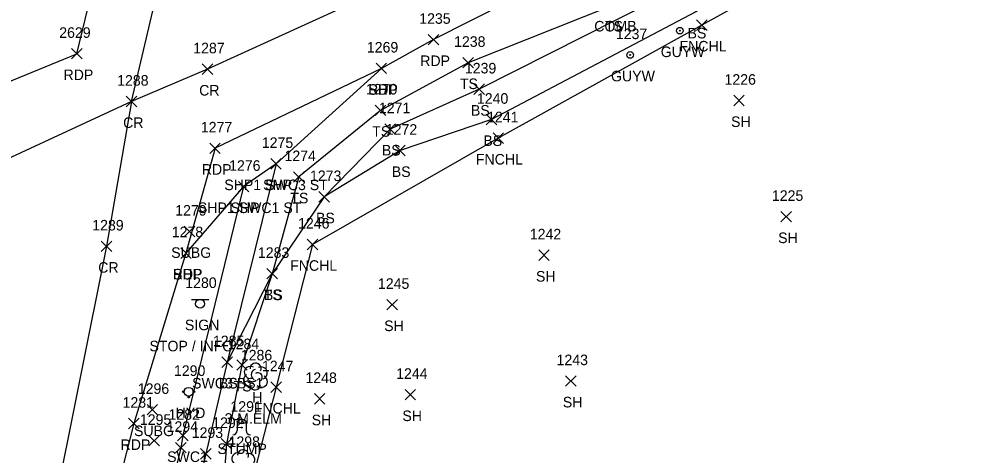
# Model space of a CAD drawing. Extents: x 1477930 to 1480780, y 774090 to 784647.
# Drawn here: x 1479397 to 1479576.9, y 774628 to 774710.6 of the extents above; entities that cross this region are included whole.
import ezdxf

# ---------------------------------------------------------------- set-up
doc = ezdxf.new("R2010")
doc.units = 0
for name, color, linetype in [('L_A', 7, 'Continuous'), ('L_C', 7, 'Continuous'), ('L_I', 7, 'Continuous'), ('L_TIC', 7, 'Continuous'), ('LELB', 7, 'Continuous'), ('LFNC', 7, 'Continuous'), ('LSH', 7, 'Continuous'), ('LTD', 7, 'Continuous'), ('LTS', 7, 'Continuous'), ('P_A', 7, 'Continuous'), ('P_I', 7, 'Continuous'), ('P_TIC', 7, 'Continuous'), ('PET', 7, 'Continuous'), ('PRC', 7, 'Continuous'), ('PSP', 7, 'Continuous'), ('R_A', 7, 'Continuous'), ('R_I', 7, 'Continuous'), ('R_TIC', 7, 'Continuous'), ('RSW', 7, 'Continuous'), ('S_A', 7, 'Continuous'), ('S_C', 7, 'Continuous'), ('S_I', 7, 'Continuous'), ('SSGN', 7, 'Continuous'), ('U_A', 7, 'Continuous'), ('U_I', 7, 'Continuous'), ('U_TIC', 7, 'Continuous'), ('UPGW', 7, 'Continuous'), ('UWFH', 7, 'Continuous')]:
    doc.layers.add(name, color=color, linetype=linetype)

msp = doc.modelspace()

# ---------------------------------------------------------------- linework, layer by layer
at = {"layer": 'L_TIC'}
for points in [[(1479525.46, 774708.45), (1479527.46, 774710.45)], [(1479527.46, 774708.45), (1479525.46, 774710.45)], [(1479481.17, 774701.33), (1479483.17, 774703.33)], [(1479483.17, 774701.33), (1479481.17, 774703.33)], [(1479483.23, 774696.29), (1479485.23, 774698.29)], [(1479485.23, 774696.29), (1479483.23, 774698.29)], [(1479532.49, 774694.15), (1479534.49, 774696.15)], [(1479534.49, 774694.15), (1479532.49, 774696.15)], [(1479464.55, 774692.3), (1479466.55, 774694.3)], [(1479466.55, 774692.3), (1479464.55, 774694.3)], [(1479485.59, 774690.55), (1479487.59, 774692.55)], [(1479487.59, 774690.55), (1479485.59, 774692.55)], [(1479466.35, 774688.75), (1479468.35, 774690.75)], [(1479468.35, 774688.75), (1479466.35, 774690.75)], [(1479486.86, 774687.03), (1479488.86, 774689.03)], [(1479488.86, 774687.03), (1479486.86, 774689.03)], [(1479468.23, 774684.68), (1479470.23, 774686.68)], [(1479470.23, 774684.68), (1479468.23, 774686.68)], [(1479449.04, 774679.68), (1479451.04, 774681.68)], [(1479451.04, 774679.68), (1479449.04, 774681.68)], [(1479453.86, 774675.9), (1479455.86, 774677.9)], [(1479455.86, 774675.9), (1479453.86, 774677.9)], [(1479453.86, 774675.9), (1479455.86, 774677.9)], [(1479455.86, 774675.9), (1479453.86, 774677.9)], [(1479541.41, 774672.15), (1479543.41, 774674.15)], [(1479543.41, 774672.15), (1479541.41, 774674.15)], [(1479451.66, 774666.9), (1479453.66, 774668.9)], [(1479453.66, 774666.9), (1479451.66, 774668.9)], [(1479495.53, 774664.85), (1479497.53, 774666.85)], [(1479497.53, 774664.85), (1479495.53, 774666.85)], [(1479443.99, 774661.35), (1479445.99, 774663.35)], [(1479445.99, 774661.35), (1479443.99, 774663.35)], [(1479443.99, 774661.35), (1479445.99, 774663.35)], [(1479445.99, 774661.35), (1479443.99, 774663.35)], [(1479466.75, 774655.48), (1479468.75, 774657.48)], [(1479468.75, 774655.48), (1479466.75, 774657.48)], [(1479435.47, 774644.61), (1479437.47, 774646.61)], [(1479437.47, 774644.61), (1479435.47, 774646.61)], [(1479438.28, 774644.05), (1479440.28, 774646.05)], [(1479440.28, 774644.05), (1479438.28, 774646.05)], [(1479500.61, 774641.02), (1479502.61, 774643.02)], [(1479502.61, 774641.02), (1479500.61, 774643.02)], [(1479444.76, 774639.86), (1479446.76, 774641.86)], [(1479446.76, 774639.86), (1479444.76, 774641.86)], [(1479453, 774637.64), (1479455, 774639.64)], [(1479455, 774637.64), (1479453, 774639.64)], [(1479470.19, 774638.43), (1479472.19, 774640.43)], [(1479472.19, 774638.43), (1479470.19, 774640.43)], [(1479421.62, 774629.71), (1479423.62, 774631.71)], [(1479423.62, 774629.71), (1479421.62, 774631.71)], [(1479435.33, 774629.12), (1479437.33, 774631.12)], [(1479437.33, 774629.12), (1479435.33, 774631.12)]]:
    msp.add_lwpolyline(points, dxfattribs=at)
at = {"layer": 'LELB'}
for points in [[(1479759.78, 774845.84), (1479743.76, 774848.1), (1479715.88, 774830.05), (1479665.38, 774803.72), (1479650.39, 774795.36), (1479602.85, 774770.48), (1479561.12, 774746.99), (1479522.68, 774719.79), (1479509.66, 774713.24), (1479482.17, 774702.33), (1479465.55, 774693.3), (1479450.04, 774680.68), (1479444.99, 774662.35), (1479439.28, 774645.05), (1479436.33, 774630.12), (1479434.69, 774607.73), (1479420.75, 774561.37), (1479408.24, 774515.83), (1479404.08, 774492.53), (1479401.08, 774483.2), (1479386.93, 774431.62)], [(1479759.78, 774845.84), (1479747.61, 774840.08), (1479717.72, 774826.7), (1479693.11, 774813.12), (1479667.75, 774799.87), (1479652.34, 774792.25), (1479604.7, 774766.29), (1479564.8, 774741.45), (1479523.94, 774717.4), (1479484.23, 774697.29), (1479467.35, 774689.75), (1479454.86, 774676.9), (1479444.99, 774662.35), (1479436.47, 774645.61)], [(1479755.47, 774826.43), (1479747.52, 774835), (1479732.81, 774826.8), (1479711.85, 774814.98), (1479703.35, 774801.53), (1479690.31, 774796.96), (1479675.98, 774796.31), (1479667.39, 774786.04), (1479656.48, 774787.57), (1479654.62, 774789.12), (1479607, 774760.65), (1479567.24, 774738.02), (1479525.29, 774711.93), (1479486.59, 774691.55), (1479469.23, 774685.68), (1479454.86, 774676.9)]]:
    msp.add_lwpolyline(points, dxfattribs=at)
at = {"layer": 'LFNC'}
msp.add_lwpolyline([(1479663.5, 774773.7), (1479660.34, 774780.67), (1479659.08, 774782.89), (1479609.82, 774754.99), (1479569.72, 774733.43), (1479526.46, 774709.45), (1479487.86, 774688.03), (1479452.66, 774667.9), (1479445.76, 774640.86), (1479438.34, 774612.12), (1479428.73, 774573.41), (1479420.36, 774539.52), (1479411.98, 774506.91), (1479408.88, 774492.5)], dxfattribs=at)
at = {"layer": 'LSH'}
msp.add_arc((1479439.48, 774627.96), 1.05, 335.5272, 180.9563, dxfattribs=at)
for centre, major_axis, ratio in [((1479438.64, 774627.19), (1.21, -0.51), 0.895232), ((1479440.47, 774627.1), (-1.14, -0.48), 0.949671)]:
    msp.add_ellipse(centre, major_axis=major_axis, ratio=ratio, start_param=1.570796, end_param=4.712389, dxfattribs=at)
at = {"layer": 'LTD'}
msp.add_line((1479441.81, 774642.92), (1479441.81, 774642.92), dxfattribs=at)
msp.add_line((1479441.81, 774642.92), (1479441.81, 774642.92), dxfattribs=at)
msp.add_arc((1479441.85, 774644.36), 1.05, 335.5272, 180.9563, dxfattribs=at)
for centre, major_axis, ratio, start_param, end_param in [((1479441.01, 774643.59), (1.21, -0.51), 0.895232, 1.570796, 4.712389), ((1479441.6, 774643.38), (-0.208, -0.792), 0.645439, 3.141593, 6.283185), ((1479442.85, 774643.5), (-1.14, -0.48), 0.949671, 1.570796, 4.712389), ((1479440.72, 774642.21), (0.58, -1.04), 0.959034, 3.141593, 6.283185), ((1479442.31, 774642.75), (-0.5, 0.667), 0.989748, 3.141593, 6.283185), ((1479442.81, 774642.09), (-1.09, 0.79), 0.841452, 1.570796, 4.712389), ((1479441.81, 774641.42), (0.26, 1.06), 0.942809, 1.570796, 4.712389), ((1479441.35, 774642.17), (-0.625, -0.083), 0.423636, 0, 3.141593)]:
    msp.add_ellipse(centre, major_axis=major_axis, ratio=ratio, start_param=start_param, end_param=end_param, dxfattribs=at)
at = {"layer": 'LTS'}
for p, q in [((1479438.38, 774634.33), (1479438.38, 774632.66)), ((1479440.05, 774634.16), (1479440.05, 774634.33)), ((1479440.05, 774634.33), (1479440.05, 774632.66)), ((1479439.22, 774633.19), (1479439.22, 774633.19)), ((1479439.22, 774633.19), (1479439.22, 774633.19)), ((1479439.22, 774633.16), (1479439.22, 774633.16))]:
    msp.add_line(p, q, dxfattribs=at)
msp.add_circle((1479439.22, 774633.19), 0.0833, dxfattribs=at)
for centre, start, end in [((1479437.55, 774632.66), 270, 360), ((1479440.88, 774632.66), 180, 270)]:
    msp.add_arc(centre, 0.833, start, end, dxfattribs=at)
msp.add_ellipse((1479439.22, 774634.33), major_axis=(-0.833, 0), ratio=0.5, dxfattribs=at)
at = {"layer": 'P_TIC'}
for points in [[(1479474.57, 774705.69), (1479476.57, 774707.69)], [(1479476.57, 774705.69), (1479474.57, 774707.69)], [(1479406.96, 774703.03), (1479408.96, 774705.03)], [(1479408.96, 774703.03), (1479406.96, 774705.03)], [(1479431.73, 774700.1), (1479433.73, 774702.1)], [(1479433.73, 774700.1), (1479431.73, 774702.1)], [(1479464.7, 774700.25), (1479466.7, 774702.25)], [(1479466.7, 774700.25), (1479464.7, 774702.25)], [(1479464.7, 774700.25), (1479466.7, 774702.25)], [(1479466.7, 774700.25), (1479464.7, 774702.25)], [(1479417.32, 774693.97), (1479419.32, 774695.97)], [(1479419.32, 774693.97), (1479417.32, 774695.97)], [(1479417.32, 774693.97), (1479419.32, 774695.97)], [(1479419.32, 774693.97), (1479417.32, 774695.97)], [(1479417.32, 774693.97), (1479419.32, 774695.97)], [(1479419.32, 774693.97), (1479417.32, 774695.97)], [(1479433.17, 774685.11), (1479435.17, 774687.11)], [(1479435.17, 774685.11), (1479433.17, 774687.11)], [(1479444.73, 774682.18), (1479446.73, 774684.18)], [(1479446.73, 774682.18), (1479444.73, 774684.18)], [(1479438.59, 774677.84), (1479440.59, 774679.84)], [(1479440.59, 774677.84), (1479438.59, 774679.84)], [(1479412.6, 774666.54), (1479414.6, 774668.54)], [(1479414.6, 774666.54), (1479412.6, 774668.54)], [(1479427.66, 774665.26), (1479429.66, 774667.26)], [(1479429.66, 774665.26), (1479427.66, 774667.26)], [(1479427.66, 774665.26), (1479429.66, 774667.26)], [(1479429.66, 774665.26), (1479427.66, 774667.26)], [(1479417.77, 774632.96), (1479419.77, 774634.96)], [(1479419.77, 774632.96), (1479417.77, 774634.96)]]:
    msp.add_lwpolyline(points, dxfattribs=at)
at = {"layer": 'PET'}
for points in [[(1479234.45, 774632.83), (1479239.1, 774628.15), (1479289.14, 774648.12), (1479321.9, 774663.73), (1479351.45, 774679.08), (1479366.99, 774687.18), (1479407.96, 774704.03), (1479416.46, 774738.94), (1479422.81, 774766.95), (1479432.79, 774813.6), (1479435.56, 774829.5), (1479438.63, 774843.63), (1479441.63, 774858.96), (1479447.93, 774875.75)], [(1479713.99, 774833.47), (1479663.95, 774806), (1479649, 774797.94), (1479602.12, 774772.9), (1479559.82, 774750.06), (1479518.06, 774728.17), (1479475.57, 774706.69), (1479465.7, 774701.25), (1479434.17, 774686.11), (1479428.66, 774666.26), (1479418.77, 774633.96), (1479413.82, 774614.69), (1479404.23, 774566.57), (1479393.7, 774517.71), (1479389.34, 774499.77)]]:
    msp.add_lwpolyline(points, dxfattribs=at)
at = {"layer": 'PRC'}
for points in [[(1480015.89, 775005.87), (1479971.79, 774982.46), (1479929.14, 774959.03), (1479892.61, 774942.34), (1479860.44, 774925.31), (1479806.49, 774896.54), (1479658.45, 774815.54), (1479643.75, 774807.57), (1479597.62, 774782.97), (1479555.61, 774761.16), (1479513.42, 774740.32), (1479471, 774718.6), (1479432.73, 774701.1), (1479418.32, 774694.97), (1479344.83, 774660.92), (1479298.6, 774640.39), (1479262.12, 774624.4), (1479219.63, 774609.01), (1479186.74, 774593.83)], [(1479418.32, 774694.97), (1479429.98, 774744.43), (1479441.03, 774796.84), (1479452.21, 774846.49), (1479460.29, 774885.01)], [(1479418.32, 774694.97), (1479413.6, 774667.54), (1479403.41, 774616.88), (1479393.18, 774569.31), (1479382.15, 774520.62), (1479370.95, 774473.44), (1479362, 774437.8), (1479350.26, 774392.93), (1479347.88, 774382.5), (1479334.29, 774330.6), (1479333.84, 774328.63), (1479325.02, 774295.54), (1479313.51, 774250.57), (1479296.99, 774187.82), (1479284.93, 774140.68)]]:
    msp.add_lwpolyline(points, dxfattribs=at)
at = {"layer": 'PSP'}
msp.add_lwpolyline([(1479465.7, 774701.25), (1479445.73, 774683.18), (1479439.59, 774678.84), (1479428.66, 774666.26)], dxfattribs=at)
at = {"layer": 'R_TIC'}
for points in [[(1479444.73, 774682.18), (1479446.73, 774684.18)], [(1479446.73, 774682.18), (1479444.73, 774684.18)], [(1479438.59, 774677.84), (1479440.59, 774679.84)], [(1479440.59, 774677.84), (1479438.59, 774679.84)], [(1479435.47, 774644.61), (1479437.47, 774646.61)], [(1479437.47, 774644.61), (1479435.47, 774646.61)], [(1479427.06, 774630.68), (1479429.06, 774632.68)], [(1479429.06, 774630.68), (1479427.06, 774632.68)], [(1479426.69, 774628.39), (1479428.69, 774630.39)], [(1479428.69, 774628.39), (1479426.69, 774630.39)], [(1479431.44, 774627.24), (1479433.44, 774629.24)], [(1479433.44, 774627.24), (1479431.44, 774629.24)]]:
    msp.add_lwpolyline(points, dxfattribs=at)
at = {"layer": 'RSW'}
for points in [[(1479445.73, 774683.18), (1479436.47, 774645.61), (1479432.44, 774628.24), (1479428.42, 774611.14), (1479416.86, 774563.55), (1479405.32, 774516.05), (1479399.83, 774493.77), (1479397.14, 774483.55), (1479383.7, 774432.42), (1479378.78, 774414.66), (1479376, 774403.93), (1479368.41, 774376.23), (1479354.39, 774323.87), (1479354.03, 774322.36), (1479349.26, 774304.31), (1479346.2, 774292.81), (1479333.15, 774243.56), (1479321.64, 774199.64), (1479319.46, 774190.5)], [(1479439.59, 774678.84), (1479428.06, 774631.68), (1479427.69, 774629.39), (1479423.62, 774612.61), (1479412.13, 774564.62), (1479400.05, 774515.9), (1479395.35, 774496.7), (1479392.07, 774484.83), (1479378.7, 774433.47), (1479373.97, 774416.64), (1479370.99, 774405.04), (1479364.01, 774378.3), (1479349.72, 774325.26), (1479349.32, 774323.81), (1479344.48, 774305.55), (1479341.14, 774293.48), (1479328.32, 774245.21), (1479314.62, 774191.4)]]:
    msp.add_lwpolyline(points, dxfattribs=at)
at = {"layer": 'SSGN'}
for p, q in [((1479429.68, 774657.49), (1479433.01, 774657.49)), ((1479431.33, 774656.66), (1479431.33, 774656.66))]:
    msp.add_line(p, q, dxfattribs=at)
msp.add_circle((1479431.33, 774656.66), 0.833, dxfattribs=at)
at = {"layer": 'U_TIC'}
for points in [[(1479428.33, 774669.35), (1479430.33, 774671.35)], [(1479430.33, 774669.35), (1479428.33, 774671.35)], [(1479421.28, 774635.58), (1479423.28, 774637.58)], [(1479423.28, 774635.58), (1479421.28, 774637.58)]]:
    msp.add_lwpolyline(points, dxfattribs=at)
at = {"layer": 'UPGW'}
for centre, radius in [((1479522.25, 774708.39), 0.625), ((1479522.25, 774708.39), 0.0833), ((1479512.84, 774703.79), 0.625), ((1479512.84, 774703.79), 0.0833)]:
    msp.add_circle(centre, radius, dxfattribs=at)
at = {"layer": 'UWFH'}
msp.add_line((1479429.17, 774639.98), (1479429.17, 774639.98), dxfattribs=at)
for centre, radius in [((1479429.17, 774639.98), 0.833), ((1479428.17, 774639.98), 0.167), ((1479429.17, 774638.98), 0.167), ((1479430.17, 774639.98), 0.167)]:
    msp.add_circle(centre, radius, dxfattribs=at)

# ---------------------------------------------------------------- texts
at = {"layer": 'L_A'}
for s, p in [('TS', (1479508.07, 774708.24)), ('BS', (1479523.73, 774706.93)), ('FNCHL', (1479522.21, 774704.45)), ('TS', (1479480.58, 774697.33)), ('BS', (1479482.67, 774692.29)), ('SH', (1479531.98, 774690.15)), ('TS', (1479463.96, 774688.3)), ('BS', (1479485.03, 774686.55)), ('BS', (1479465.79, 774684.75)), ('FNCHL', (1479483.61, 774683.03)), ('BS', (1479467.67, 774680.68)), ('TS', (1479448.44, 774675.68)), ('BS', (1479453.31, 774671.9)), ('BS', (1479453.31, 774671.9)), ('SH', (1479540.9, 774668.15)), ('FNCHL', (1479448.41, 774662.9)), ('SH', (1479495.01, 774660.85)), ('TS', (1479443.4, 774657.35)), ('BS', (1479443.43, 774657.35)), ('SH', (1479466.23, 774651.48)), ('BS', (1479434.91, 774640.61)), ('TS', (1479437.69, 774640.05)), ('H', (1479441.24, 774637.92)), ('SH', (1479500.09, 774637.02)), ('FNCHL', (1479441.51, 774635.86)), ('SH', (1479452.49, 774633.64)), ('SH', (1479469.68, 774634.43)), ('STUMP', (1479434.64, 774628.19))]:
    msp.add_text(s, height=2, dxfattribs=at).set_placement(p)
at = {"layer": 'L_C'}
msp.add_text('3-M.ELM', height=2, dxfattribs=at).set_placement((1479436, 774633.92))
at = {"layer": 'L_I'}
for s, p in [('1238', (1479479.48, 774705.33)), ('1239', (1479481.53, 774700.29)), ('1226', (1479530.74, 774698.15)), ('1270', (1479462.77, 774696.3)), ('1240', (1479483.81, 774694.55)), ('1271', (1479465.23, 774692.75)), ('1241', (1479485.74, 774691.03)), ('1272', (1479466.54, 774688.68)), ('1274', (1479447.34, 774683.68)), ('1273', (1479452.17, 774679.9)), ('1273', (1479452.17, 774679.9)), ('1225', (1479539.72, 774676.15)), ('1246', (1479449.91, 774670.9)), ('1242', (1479493.83, 774668.85)), ('1283', (1479442.3, 774665.35)), ('1283', (1479442.3, 774665.35)), ('1245', (1479465.05, 774659.48)), ('1285', (1479433.78, 774648.61)), ('1284', (1479436.59, 774648.05)), ('1286', (1479439.06, 774645.92)), ('1247', (1479443.07, 774643.86)), ('1243', (1479498.91, 774645.02)), ('1244', (1479468.5, 774642.43)), ('1248', (1479451.31, 774641.64)), ('1291', (1479437.09, 774636.19)), ('1295', (1479419.92, 774633.71)), ('1292', (1479433.64, 774633.12)), ('1298', (1479436.74, 774629.52))]:
    msp.add_text(s, height=2, dxfattribs=at).set_placement(p)
at = {"layer": 'P_A'}
for s, p in [('RDP', (1479473.06, 774701.69)), ('RDP', (1479405.45, 774699.03)), ('CR', (1479431.16, 774696.1)), ('SHP', (1479463.23, 774696.25)), ('RDP', (1479463.18, 774696.25)), ('CR', (1479416.75, 774689.97)), ('CR', (1479416.75, 774689.97)), ('CR', (1479416.75, 774689.97)), ('RDP', (1479431.66, 774681.11)), ('SHP', (1479443.27, 774678.18)), ('SHP', (1479437.12, 774673.84)), ('CR', (1479412.03, 774662.54)), ('SHP', (1479426.2, 774661.26)), ('RDP', (1479426.15, 774661.26)), ('RDP', (1479416.26, 774628.96))]:
    msp.add_text(s, height=2, dxfattribs=at).set_placement(p)
at = {"layer": 'P_I'}
for s, p in [('1235', (1479472.88, 774709.69)), ('2629', (1479404.64, 774707.03)), ('1287', (1479430.04, 774704.1)), ('1269', (1479462.95, 774704.25)), ('1269', (1479462.95, 774704.25)), ('1288', (1479415.62, 774697.97)), ('1288', (1479415.62, 774697.97)), ('1288', (1479415.62, 774697.97)), ('1277', (1479431.48, 774689.11)), ('1275', (1479443.04, 774686.18)), ('1276', (1479436.84, 774681.84)), ('1289', (1479410.9, 774670.54)), ('1278', (1479425.97, 774669.26)), ('1278', (1479425.97, 774669.26)), ('1281', (1479416.65, 774636.96))]:
    msp.add_text(s, height=2, dxfattribs=at).set_placement(p)
at = {"layer": 'R_A'}
for s, p in [('SHP1 SWC3 ST', (1479435.93, 774678.18)), ('SHP1 SWC1 ST', (1479430.92, 774673.84)), ('SWC3 BS1', (1479429.82, 774640.61)), ('SWC1', (1479425.09, 774626.68))]:
    msp.add_text(s, height=2, dxfattribs=at).set_placement(p)
at = {"layer": 'R_I'}
for s, p in [('1275', (1479443.04, 774686.18)), ('1276', (1479436.84, 774681.84)), ('1285', (1479433.78, 774648.61)), ('1282', (1479425.36, 774634.68)), ('1294', (1479425, 774632.39)), ('1293', (1479429.75, 774631.24))]:
    msp.add_text(s, height=2, dxfattribs=at).set_placement(p)
at = {"layer": 'S_A'}
msp.add_text('SIGN', height=2, dxfattribs=at).set_placement((1479428.46, 774651.64))
at = {"layer": 'S_C'}
msp.add_text('STOP / INFO', height=2, dxfattribs=at).set_placement((1479421.74, 774647.64))
at = {"layer": 'S_I'}
msp.add_text('1280', height=2, dxfattribs=at).set_placement((1479428.53, 774659.64))
at = {"layer": 'U_A'}
for s, p in [('COMB', (1479506.05, 774708.24)), ('GUYW', (1479518.65, 774703.39)), ('GUYW', (1479509.23, 774698.79)), ('SUBG', (1479425.86, 774665.35)), ('HYD', (1479426.69, 774634.98)), ('SUBG', (1479418.81, 774631.58))]:
    msp.add_text(s, height=2, dxfattribs=at).set_placement(p)
at = {"layer": 'U_I'}
for s, p in [('1237', (1479510.15, 774706.79)), ('1279', (1479426.63, 774673.35)), ('1290', (1479426.39, 774642.98)), ('1296', (1479419.53, 774639.58))]:
    msp.add_text(s, height=2, dxfattribs=at).set_placement(p)

doc.saveas('drawing.dxf')
